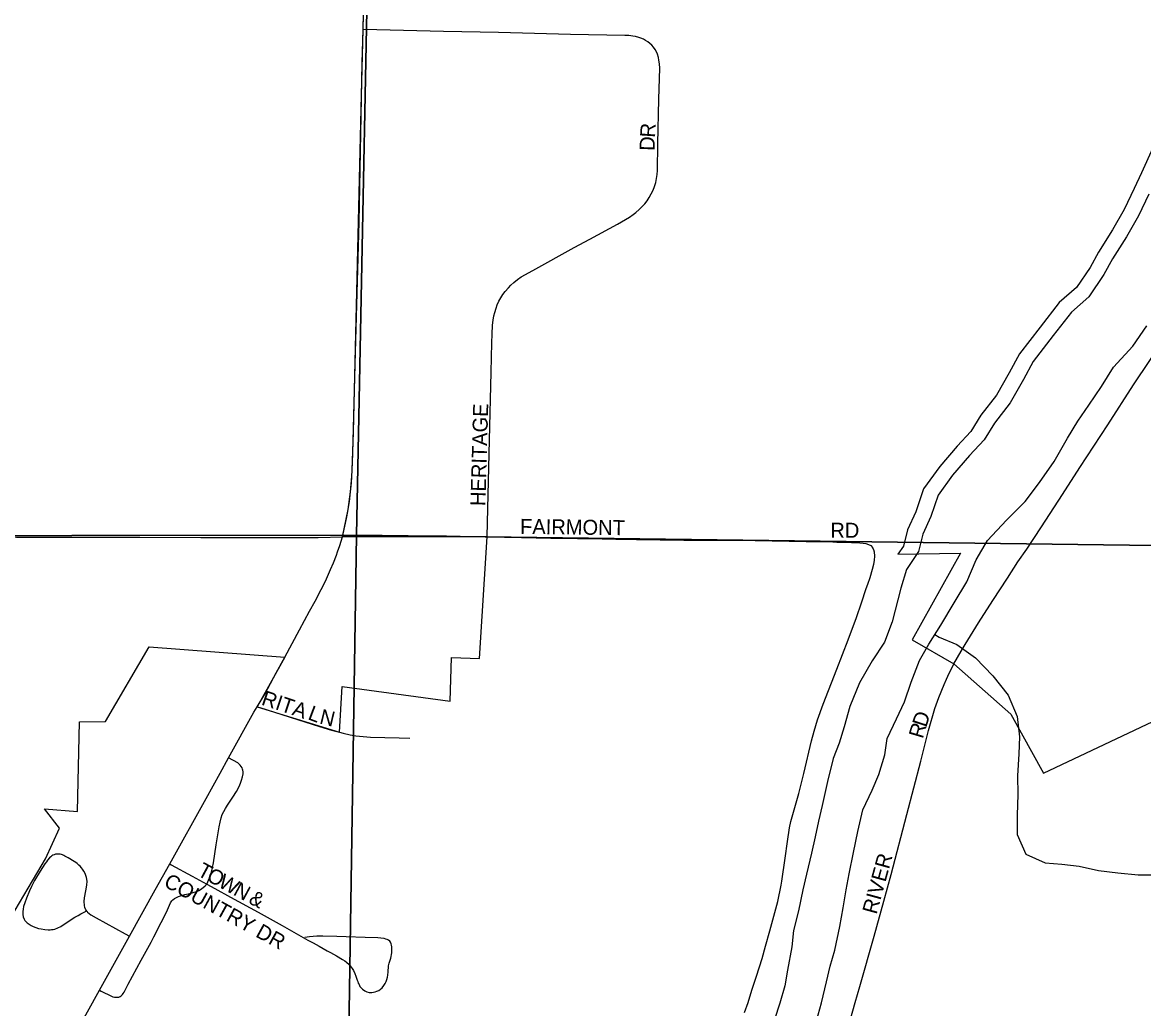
# Model space of a CAD drawing. Extents: x 0 to 34, y 0 to 22.
# Drawn here: x 5.9157 to 6.2693, y 19.2755 to 19.5866 of the extents above; entities that cross this region are included whole.
import ezdxf

# ---------------------------------------------------------------- set-up
doc = ezdxf.new("R2010")
doc.units = 0
for name, color, linetype in [('GM_X_City_Street', 7, 'Continuous'), ('GM_X_City_Street_Text', 7, 'Continuous'), ('GM_X_Corporation', 7, 'Continuous'), ('GM_X_Major_River', 7, 'Continuous'), ('GM_X_Minor_River', 7, 'Continuous'), ('GM_X_Section', 7, 'Continuous'), ('GM_X_State_Route', 7, 'Continuous'), ('GM_X_Township_Road', 7, 'Continuous')]:
    doc.layers.add(name, color=color, linetype=linetype)

msp = doc.modelspace()

# ---------------------------------------------------------------- linework, layer by layer
at = {"layer": 'GM_X_City_Street'}
for points in [[(6.06226, 19.42434), (6.06243, 19.43326), (6.063, 19.45479), (6.06355, 19.47623), (6.06369, 19.48554), (6.06381, 19.48829), (6.06398, 19.49109), (6.06414, 19.49265), (6.06438, 19.49401), (6.06463, 19.49506), (6.06505, 19.49645), (6.06541, 19.49752), (6.06595, 19.49869), (6.06654, 19.4997), (6.06723, 19.50076), (6.06798, 19.50172), (6.06893, 19.50289), (6.06971, 19.50367), (6.07068, 19.50458), (6.07182, 19.50552), (6.07295, 19.50629), (6.07661, 19.50836), (6.08967, 19.51554), (6.09459, 19.5182), (6.10332, 19.52296), (6.10713, 19.52513), (6.10833, 19.52595), (6.10919, 19.52663), (6.1102, 19.52753), (6.11104, 19.52836), (6.11195, 19.52938), (6.11267, 19.53032), (6.11339, 19.5314), (6.11401, 19.53249), (6.11458, 19.5337), (6.11503, 19.53483), (6.1154, 19.53605), (6.11567, 19.5373), (6.11585, 19.53857), (6.11597, 19.53982), (6.11605, 19.54824), (6.11642, 19.56232), (6.11667, 19.57218), (6.11661, 19.57349), (6.11644, 19.57471), (6.11628, 19.57556), (6.11594, 19.5766), (6.11562, 19.57733), (6.11521, 19.57807), (6.11471, 19.57875), (6.1142, 19.57937), (6.1136, 19.57994), (6.11296, 19.58045), (6.11224, 19.58091), (6.11157, 19.5813), (6.11077, 19.58165), (6.11004, 19.58187), (6.10904, 19.58212), (6.10816, 19.58228), (6.1069, 19.58241), (6.10564, 19.58248), (6.08853, 19.58278), (6.06586, 19.58337), (6.04847, 19.58376), (6.02742, 19.58425), (6.0231, 19.58435)], [(6.0166, 19.4243), (6.02767, 19.42471), (6.03639, 19.42475), (6.04947, 19.42462), (6.06226, 19.42434)], [(6.06226, 19.42434), (6.07303, 19.42408), (6.08237, 19.42394), (6.09076, 19.42381), (6.09418, 19.42377), (6.10286, 19.42355), (6.10939, 19.42347), (6.12432, 19.42328), (6.13366, 19.42328), (6.14142, 19.42322), (6.1629, 19.42288), (6.17128, 19.42269), (6.17253, 19.42268), (6.17532, 19.42261), (6.17717, 19.42257), (6.17873, 19.42254), (6.18083, 19.42236), (6.18171, 19.42223), (6.18252, 19.42195), (6.18323, 19.42155), (6.18378, 19.42097)], [(6.14342, 19.27425), (6.14454, 19.27745), (6.14572, 19.28131), (6.1472, 19.28571), (6.14894, 19.29134), (6.15009, 19.29521), (6.15144, 19.29999), (6.15392, 19.30928), (6.15503, 19.31444), (6.15521, 19.3157), (6.15621, 19.32297), (6.15696, 19.3282), (6.15759, 19.33256), (6.15807, 19.33454), (6.15867, 19.33677), (6.16051, 19.34334), (6.16211, 19.34967), (6.16457, 19.35997), (6.16539, 19.36298), (6.16649, 19.36656), (6.16827, 19.37156), (6.17255, 19.38259), (6.17616, 19.39185), (6.17874, 19.39885), (6.18036, 19.40354), (6.18178, 19.40798), (6.18233, 19.40944), (6.183, 19.4115), (6.18375, 19.41414), (6.18421, 19.41565), (6.18442, 19.41685), (6.18454, 19.41831), (6.18441, 19.41943), (6.18418, 19.42024), (6.18378, 19.42097)], [(6.20708, 19.37938), (6.2075, 19.38035), (6.20939, 19.38429), (6.21171, 19.38821)], [(6.17485, 19.26505), (6.17836, 19.27748), (6.17979, 19.28252), (6.1843, 19.29835), (6.18735, 19.30938), (6.18968, 19.31781), (6.19466, 19.33676), (6.19898, 19.35361), (6.20142, 19.36326), (6.20346, 19.37014), (6.20469, 19.37368), (6.20635, 19.37771), (6.20708, 19.37938)], [(5.98972, 19.37069), (5.99051, 19.37044), (6.00933, 19.36454), (6.01315, 19.36334), (6.01564, 19.36266)], [(6.01564, 19.36266), (6.0168, 19.36234), (6.01899, 19.36183), (6.02085, 19.36152), (6.02313, 19.36129), (6.02545, 19.36115), (6.03448, 19.3609), (6.03789, 19.36077)], [(5.97383, 19.31476), (5.97468, 19.31676), (5.97527, 19.3185), (5.97563, 19.32004), (5.97589, 19.32152), (5.97679, 19.32719), (5.97768, 19.33287), (5.97799, 19.33434), (5.97834, 19.33564), (5.97871, 19.3367), (5.97915, 19.33772), (5.97968, 19.33865), (5.9803, 19.33963), (5.982, 19.34217), (5.98315, 19.34397), (5.984, 19.34557), (5.98444, 19.34665), (5.98478, 19.34759), (5.98505, 19.3486), (5.98525, 19.34959), (5.98529, 19.35017), (5.9852, 19.3507), (5.98511, 19.35104), (5.98495, 19.35147), (5.98467, 19.35192), (5.98438, 19.3523), (5.98397, 19.35274), (5.98356, 19.35307), (5.98068, 19.35457)], [(5.92671, 19.32424), (5.92658, 19.32424), (5.92615, 19.32418), (5.92569, 19.32406), (5.92529, 19.32387), (5.92495, 19.32365), (5.92458, 19.32338), (5.92422, 19.32302), (5.9236, 19.32234), (5.92324, 19.32185), (5.92279, 19.3212), (5.92125, 19.31885), (5.91948, 19.31594), (5.9185, 19.31402), (5.91787, 19.31263), (5.91697, 19.31034), (5.91644, 19.30891), (5.91606, 19.3077), (5.91588, 19.30687), (5.91578, 19.30617), (5.91575, 19.30567), (5.9158, 19.305), (5.91586, 19.30475)], [(5.93594, 19.30632), (5.93593, 19.30633), (5.93568, 19.30669), (5.93539, 19.30738), (5.93522, 19.30802), (5.93511, 19.30925), (5.93522, 19.31049), (5.93564, 19.31264), (5.936, 19.31446), (5.93604, 19.3157), (5.93589, 19.31691), (5.93547, 19.31808), (5.93502, 19.31891), (5.9346, 19.31949), (5.9343, 19.31989), (5.93385, 19.32039), (5.93346, 19.3208), (5.93294, 19.32125), (5.9325, 19.32159), (5.93198, 19.32194), (5.93011, 19.32304), (5.92909, 19.32363), (5.92873, 19.32381), (5.9283, 19.32399), (5.92798, 19.32409), (5.92753, 19.32421), (5.92706, 19.32425), (5.92671, 19.32424)], [(5.96213, 19.32116), (5.96262, 19.32089), (5.96916, 19.31732), (5.97383, 19.31476)], [(5.94001, 19.28128), (5.94052, 19.28103), (5.94379, 19.27942), (5.9442, 19.27924), (5.94467, 19.27912), (5.94512, 19.27908), (5.94559, 19.27909), (5.94603, 19.27916), (5.94647, 19.27935), (5.94679, 19.27957), (5.94719, 19.27992), (5.94745, 19.28025), (5.94776, 19.28069), (5.94907, 19.28326), (5.95307, 19.29077), (5.9563, 19.2965), (5.95712, 19.29812), (5.95942, 19.30267), (5.96108, 19.30595), (5.96235, 19.30892), (5.96276, 19.30951), (5.96314, 19.30981), (5.96363, 19.31023), (5.96425, 19.31056), (5.96494, 19.31086), (5.96691, 19.31145), (5.96846, 19.31185), (5.97059, 19.31246), (5.97132, 19.31279), (5.97214, 19.31331), (5.97329, 19.31419), (5.97383, 19.31476)], [(5.97383, 19.31476), (5.97638, 19.31335), (5.98129, 19.3107), (5.98998, 19.30591), (5.9976, 19.30172), (6.00569, 19.29712), (6.00735, 19.29627), (6.00922, 19.29525), (6.01182, 19.29378), (6.01289, 19.29324), (6.01474, 19.29213), (6.01661, 19.29105), (6.01736, 19.29055), (6.01787, 19.2902), (6.01877, 19.28938), (6.01971, 19.2882), (6.0201, 19.28751), (6.0205, 19.28654), (6.02082, 19.28574), (6.02107, 19.2851), (6.02129, 19.28448), (6.02143, 19.28401), (6.02158, 19.28356), (6.02185, 19.28307), (6.02214, 19.28253), (6.02248, 19.28207), (6.02292, 19.28163), (6.02364, 19.28109), (6.0243, 19.28083), (6.02505, 19.28063), (6.0259, 19.28061), (6.02693, 19.28077), (6.0275, 19.28097), (6.02808, 19.28124), (6.02857, 19.28159), (6.02911, 19.2821), (6.0297, 19.2828), (6.03009, 19.2834), (6.03036, 19.28404), (6.03062, 19.28474), (6.03078, 19.28542), (6.03094, 19.28607), (6.03107, 19.28707), (6.03106, 19.28774), (6.0311, 19.28827), (6.03118, 19.28899), (6.03139, 19.28983), (6.03188, 19.29137), (6.03202, 19.29197), (6.03212, 19.29261), (6.03219, 19.29312), (6.03223, 19.2938), (6.03223, 19.2944), (6.03217, 19.29499), (6.03211, 19.2955), (6.03196, 19.29598), (6.03171, 19.29648), (6.0315, 19.29675), (6.03112, 19.29707), (6.03075, 19.29726), (6.03025, 19.29746), (6.02974, 19.29763), (6.02867, 19.29777), (6.02773, 19.29779), (6.02375, 19.29793), (6.01776, 19.29813), (6.01484, 19.29823), (6.01046, 19.29831), (6.00857, 19.29835), (6.00741, 19.29828), (6.00624, 19.29815), (6.0047, 19.29791)], [(5.91586, 19.30475), (5.91594, 19.30442), (5.9162, 19.30376), (5.91647, 19.3033), (5.91674, 19.30296), (5.91716, 19.30256), (5.91777, 19.30211), (5.91841, 19.30174), (5.91905, 19.30142), (5.9199, 19.3011), (5.92072, 19.30081), (5.92162, 19.30064), (5.92274, 19.30049), (5.92383, 19.30041), (5.92442, 19.30041), (5.92487, 19.30043), (5.92537, 19.30049), (5.92593, 19.30062), (5.92684, 19.30094), (5.92779, 19.30142), (5.92887, 19.30213), (5.93, 19.30291), (5.93131, 19.3038), (5.93223, 19.30437), (5.9332, 19.30491), (5.93411, 19.30537), (5.93531, 19.30599), (5.93594, 19.30632), (5.93622, 19.30597), (5.93672, 19.30549), (5.93728, 19.30505), (5.93888, 19.30411), (5.94808, 19.29914), (5.94948, 19.29838)]]:
    msp.add_lwpolyline(points, dxfattribs=at)
at = {"layer": 'GM_X_Corporation'}
for points in [[(5.90505, 19.29266), (5.92294, 19.3227), (5.92735, 19.33243), (5.9226, 19.33854), (5.93304, 19.33768), (5.93363, 19.36601), (5.94188, 19.36604), (5.95568, 19.38959), (5.9984, 19.3864), (5.98972, 19.37069), (6.01564, 19.36266), (6.01648, 19.37712), (6.05063, 19.37245), (6.05101, 19.38625), (6.0598, 19.38598), (6.06226, 19.42433), (6.0166, 19.4243), (6.01845, 19.43289), (6.01919, 19.43846), (6.01955, 19.44333), (6.01964, 19.44537), (6.02005, 19.45735), (6.02263, 19.56378), (6.0231, 19.58435), (6.02387, 19.62001)], [(6.27217, 19.54702), (6.26863, 19.53908), (6.26635, 19.53421), (6.26318, 19.52759), (6.25949, 19.5212), (6.25505, 19.51415), (6.25242, 19.50931), (6.2481, 19.50299), (6.24269, 19.49819), (6.23669, 19.49047), (6.23015, 19.48203), (6.22692, 19.47606), (6.2229, 19.46902), (6.21798, 19.46265), (6.21485, 19.45754), (6.21053, 19.45291), (6.20501, 19.44647), (6.19988, 19.4395), (6.19741, 19.43221), (6.19483, 19.42653), (6.19357, 19.42142), (6.19182, 19.41883), (6.2115, 19.41916), (6.19628, 19.39182), (6.20939, 19.3843), (6.22737, 19.36841), (6.2377, 19.34976), (6.27223, 19.36612)]]:
    msp.add_lwpolyline(points, dxfattribs=at)
at = {"layer": 'GM_X_Major_River'}
for points in [[(6.27097, 19.5324), (6.26771, 19.52559), (6.26388, 19.51897), (6.25948, 19.51197), (6.2568, 19.50705), (6.25202, 19.50005), (6.2465, 19.49515), (6.24077, 19.48778), (6.23447, 19.47965), (6.2314, 19.47398), (6.22719, 19.4666), (6.22223, 19.46017), (6.21897, 19.45488), (6.2144, 19.44997), (6.20906, 19.44373), (6.20447, 19.4375), (6.20216, 19.43068), (6.19966, 19.42519), (6.1983, 19.41969), (6.19448, 19.41402), (6.19274, 19.40814), (6.19002, 19.39753), (6.18752, 19.39109), (6.18369, 19.38522), (6.17967, 19.37822), (6.17659, 19.37084), (6.17485, 19.36439), (6.1733, 19.35928), (6.17138, 19.35435), (6.16963, 19.34715), (6.16788, 19.33956), (6.16671, 19.33464), (6.16573, 19.32971), (6.16456, 19.32459), (6.16301, 19.31795), (6.16184, 19.31302), (6.16047, 19.30639), (6.15892, 19.30013), (6.15832, 19.29501), (6.15695, 19.28761), (6.15616, 19.28268), (6.15461, 19.27719), (6.15287, 19.27207)], [(6.16613, 19.27161), (6.16768, 19.2773), (6.16924, 19.28393), (6.1704, 19.28886), (6.17195, 19.29398), (6.17351, 19.30137), (6.17449, 19.30725), (6.17548, 19.31294), (6.17646, 19.31806), (6.17782, 19.3247), (6.17919, 19.33133), (6.18075, 19.33816), (6.18363, 19.34441), (6.18574, 19.34933), (6.18767, 19.35558), (6.18846, 19.36071), (6.19134, 19.36695), (6.19384, 19.37225), (6.19596, 19.37851), (6.19865, 19.38532), (6.20153, 19.39043), (6.20535, 19.39649), (6.20956, 19.40349), (6.21358, 19.41011), (6.21647, 19.41711), (6.2201, 19.42317), (6.22601, 19.42959), (6.23192, 19.43544), (6.2365, 19.44148), (6.24109, 19.4481), (6.2453, 19.45548), (6.24856, 19.46078), (6.252, 19.46588), (6.25601, 19.47174), (6.25984, 19.4778), (6.26594, 19.48441), (6.27033, 19.49083)]]:
    msp.add_lwpolyline(points, dxfattribs=at)
at = {"layer": 'GM_X_Minor_River'}
msp.add_lwpolyline([(6.20347, 19.39351), (6.20476, 19.39269), (6.21043, 19.39038), (6.21627, 19.38617), (6.22173, 19.38044), (6.22662, 19.37434), (6.22942, 19.36768), (6.23013, 19.36122), (6.22991, 19.3559), (6.22949, 19.34888), (6.22964, 19.343), (6.22941, 19.33655), (6.22938, 19.33047), (6.23218, 19.32419), (6.23822, 19.32149), (6.24352, 19.32108), (6.24901, 19.32048), (6.25506, 19.31912), (6.26112, 19.31832), (6.26755, 19.31772), (6.27437, 19.31768)], dxfattribs=at)
at = {"layer": 'GM_X_Section'}
for points in [[(6.0309, 19.9267), (6.3062, 19.92555), (6.32314, 19.93528), (6.53817, 19.93156), (6.52479, 19.41836), (6.02102, 19.42485)], [(5.49542, 19.92414), (6.0309, 19.9267), (6.02102, 19.42485), (5.48234, 19.42421)], [(6.02102, 19.42485), (6.01835, 19.24752), (5.47758, 19.24709), (5.48234, 19.42421)]]:
    msp.add_lwpolyline(points, close=True, dxfattribs=at)
msp.add_lwpolyline([(6.01835, 19.24752), (6.02102, 19.42485), (6.52479, 19.41836)], dxfattribs=at)
at = {"layer": 'GM_X_State_Route'}
for points in [[(6.0166, 19.4243), (6.01761, 19.42865), (6.018, 19.43065), (6.01845, 19.43289), (6.01888, 19.43546), (6.01919, 19.43846), (6.01946, 19.4413), (6.01964, 19.44537), (6.01988, 19.45059), (6.0207, 19.48257), (6.02189, 19.52356), (6.02281, 19.57387), (6.0231, 19.58435), (6.02348, 19.5987), (6.02387, 19.62001)], [(6.01507, 19.41959), (6.01575, 19.42159), (6.0166, 19.4243)], [(5.9984, 19.38639), (6.0031, 19.39502), (6.00625, 19.40083), (6.00802, 19.40404), (6.00986, 19.40774), (6.01122, 19.41037), (6.01287, 19.41398), (6.01377, 19.41613), (6.01472, 19.41858), (6.01507, 19.41959)], [(5.98972, 19.37069), (5.99211, 19.37468), (5.99575, 19.38145), (5.9984, 19.38639)], [(5.97804, 19.34979), (5.98068, 19.35457), (5.9887, 19.369), (5.98972, 19.37069)], [(5.91821, 19.24192), (5.92489, 19.254), (5.94001, 19.28128), (5.94948, 19.29838), (5.95758, 19.31299), (5.96213, 19.32116), (5.97361, 19.34176), (5.97804, 19.34979)]]:
    msp.add_lwpolyline(points, dxfattribs=at)
at = {"layer": 'GM_X_Township_Road'}
for points in [[(6.21171, 19.38821), (6.21298, 19.39037), (6.21727, 19.39717), (6.22176, 19.40422), (6.22635, 19.41131), (6.22966, 19.41643), (6.23249, 19.42046), (6.23709, 19.42742), (6.24373, 19.4377), (6.24918, 19.44614), (6.25802, 19.45968), (6.2661, 19.47223), (6.27666, 19.48792), (6.28268, 19.49682), (6.29722, 19.51955), (6.3009, 19.5254), (6.30434, 19.53087), (6.31123, 19.54131), (6.31615, 19.54877), (6.32175, 19.55718)], [(5.75953, 19.4246), (5.76404, 19.42462), (5.78828, 19.42462), (5.81345, 19.42456), (5.84732, 19.42435), (5.87653, 19.42432), (5.91382, 19.42426), (5.95267, 19.4242), (5.97194, 19.42411), (5.99494, 19.42409), (6.00394, 19.42411), (6.00893, 19.42409), (6.0166, 19.4243)]]:
    msp.add_lwpolyline(points, dxfattribs=at)

# ---------------------------------------------------------------- texts
at = {"layer": 'GM_X_City_Street_Text'}
for s, height, rotation, p in [('R', 0.00473, 86.404, (6.11517, 19.55013)), ('D', 0.00473, 87.9671, (6.11502, 19.546)), ('HERITAGE', 0.004735, 88.3616, (6.06168, 19.43397)), ('FAIRMONT', 0.004735, 359.2145, (6.0726, 19.42527)), ('RD', 0.004735, 0, (6.17049, 19.42402)), ('RITA', 0.004735, 341.5694, (5.99077, 19.37146)), ('L', 0.00473, 339.3097, (6.00542, 19.36685)), ('N', 0.00473, 346.2427, (6.00913, 19.36549)), ('D', 0.00473, 71.8415, (6.2007, 19.364)), ('R', 0.00473, 73.324, (6.19963, 19.36044)), ('T', 0.00473, 331.6382, (5.9705, 19.31766)), ('RIVER', 0.004735, 74.6488, (6.18505, 19.30503)), ('O', 0.00473, 331.6322, (5.97343, 19.31608)), ('W', 0.00473, 331.6378, (5.9771, 19.3141)), ('COUNTRY DR', 0.004735, 331.2443, (5.95992, 19.31427)), ('N', 0.00473, 331.6322, (5.98187, 19.31153)), ('&', 0.00473, 332.8068, (5.98672, 19.30891))]:
    msp.add_text(s, height=height, rotation=rotation, dxfattribs=at).set_placement(p)

doc.saveas('drawing.dxf')
